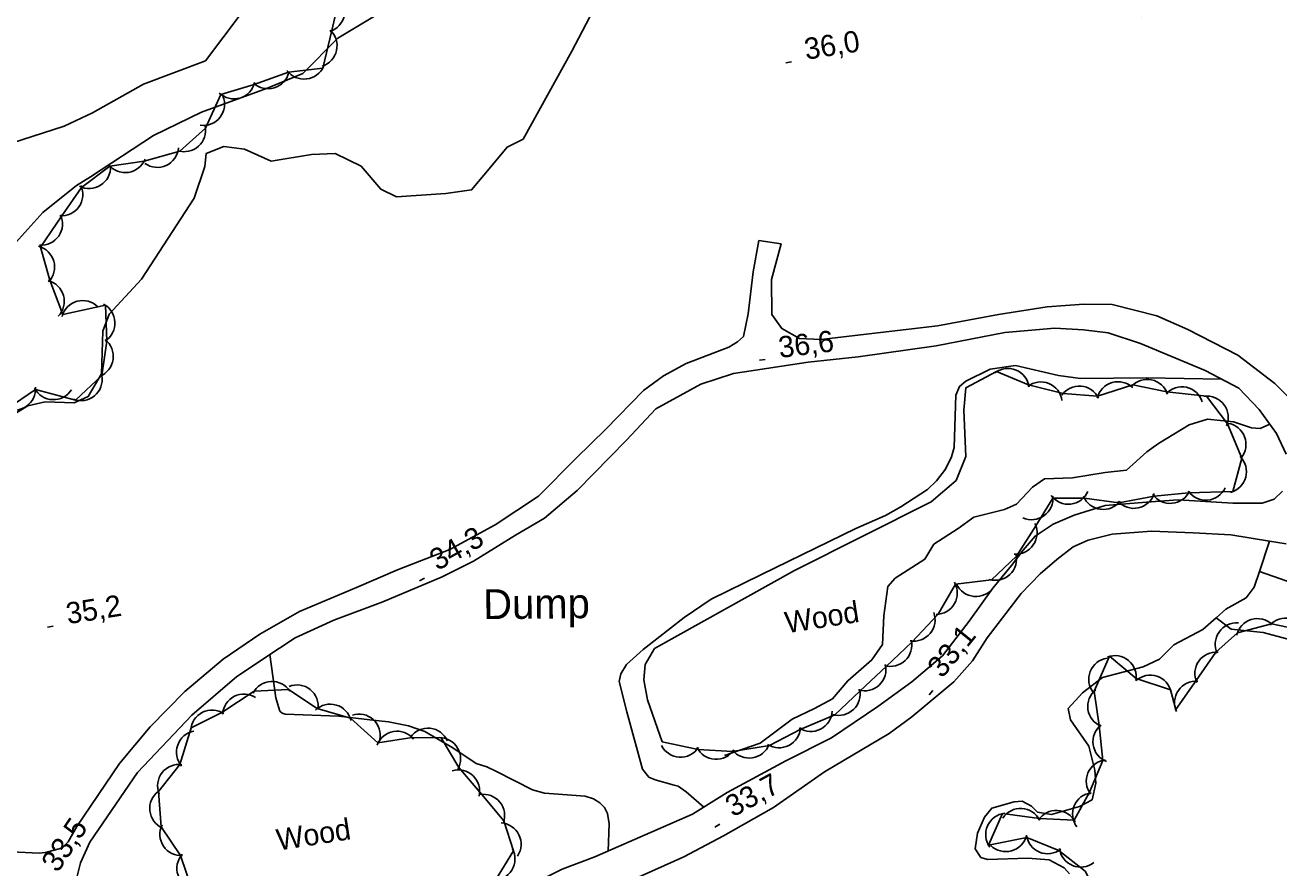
# Model space of a CAD drawing. Extents: x 646142 to 649934, y 5874075 to 5876351.
# Drawn here: x 648068.1 to 648244.3, y 5875844.9 to 5875963.3 of the extents above; entities that cross this region are included whole.
import ezdxf

# ---------------------------------------------------------------- set-up
doc = ezdxf.new("R2010")
doc.units = 0
for name, color, linetype in [('Niveau 2', 7, 'Continuous'), ('Niveau 21', 7, 'Continuous'), ('Niveau 3', 7, 'Continuous'), ('Niveau 44', 7, 'Continuous'), ('Niveau 57', 7, 'Continuous')]:
    doc.layers.add(name, color=color, linetype=linetype)

msp = doc.modelspace()

# ---------------------------------------------------------------- linework, layer by layer
at = {"layer": 'Niveau 2'}
for points in [[(648193.92, 5875992.1), (648191.37, 5875992.54), (648185.64, 5875992.74), (648180.45, 5875991.72), (648174.68, 5875990.2), (648167.73, 5875987.55), (648161.17, 5875987.29), (648154.81, 5875986.7), (648147.8, 5875984), (648141.4, 5875982.37), (648137.22, 5875980.22), (648132.3, 5875975.6), (648125, 5875970.69), (648118.64, 5875965.39), (648112.07, 5875961.45), (648107.17, 5875956.49), (648102.06, 5875954.38), (648092.92, 5875951.05), (648086.18, 5875947.79), (648077.34, 5875941.95), (648075.36, 5875940.77)], [(647999.36, 5875951.21), (648005.33, 5875949.82), (648014.71, 5875947.41), (648024.29, 5875946.86), (648029.28, 5875944.7), (648038.99, 5875939.33), (648045.26, 5875938.54), (648051.81, 5875939.95), (648058, 5875943.18), (648066.23, 5875946.68), (648073.63, 5875949.07), (648077.62, 5875950.98), (648084.78, 5875954.97), (648093.48, 5875958.28), (648098.38, 5875964.74)], [(648075.36, 5875940.77), (648070.61, 5875936.96), (648062.14, 5875927.59), (648054.38, 5875921.14), (648047.82, 5875918.35), (648041.58, 5875917.48), (648034.55, 5875917.98), (648028.66, 5875918.4), (648023.49, 5875918.53)], [(648166.4, 5875860.67), (648171.42, 5875862.38), (648175.91, 5875865.77), (648179.06, 5875867.27), (648181.59, 5875868.61), (648183.74, 5875871.18), (648187.12, 5875874.13), (648188.61, 5875876.26), (648188.83, 5875880.29), (648189.37, 5875884.4), (648190.43, 5875885.57), (648194.57, 5875888.24), (648195.84, 5875890.35), (648199.28, 5875892.56), (648201.44, 5875894.15), (648205.76, 5875895.23), (648207.47, 5875895.99), (648209.69, 5875898.39), (648211.38, 5875899.55), (648215.31, 5875899.68), (648219.94, 5875900.43), (648222.94, 5875900.78), (648225.77, 5875903.34), (648227.4, 5875904.5), (648231.72, 5875907.12), (648234.28, 5875907.94), (648237.97, 5875907.53), (648240.48, 5875906.72), (648241.72, 5875906.61), (648243.04, 5875907.2)]]:
    msp.add_lwpolyline(points, dxfattribs=at)
at = {"layer": 'Niveau 21'}
for points in [[(648247.34, 5875909.43), (648243.76, 5875912.94), (648238.56, 5875916.9), (648231.55, 5875920.5), (648227.18, 5875922.46), (648220.9, 5875924.05), (648216.9, 5875924.09), (648211.79, 5875923.71), (648204.92, 5875922.61), (648196.36, 5875921.05), (648188.33, 5875920.1), (648179.96, 5875919.12), (648179.96, 5875919.12), (648176.98, 5875919.24), (648174.48, 5875920.66), (648173.08, 5875922.61), (648173.05, 5875927.54), (648174.38, 5875932.56), (648171.27, 5875933.01), (648170.46, 5875928.6), (648169.76, 5875922.71), (648169.09, 5875919.56), (648168.23, 5875918.81), (648167.03, 5875918.03), (648161.04, 5875915.75), (648157.86, 5875914.02), (648155.04, 5875911.97), (648149.74, 5875906.53), (648145.6, 5875902.43), (648140.28, 5875897.1), (648134.18, 5875893.08)], [(648245.34, 5875903.01), (648243.98, 5875905.89), (648241.56, 5875909.26), (648238.71, 5875912.26), (648233.96, 5875914.76), (648224.88, 5875918.55), (648220.32, 5875920.04), (648216.86, 5875920.46), (648212.85, 5875920.73), (648205.82, 5875920.09), (648196.15, 5875918.21), (648185.19, 5875916.7), (648178.17, 5875915.94), (648172.31, 5875915.03), (648167.68, 5875914.34), (648163.11, 5875912.85), (648156.75, 5875909.39)], [(648156.75, 5875909.39), (648152.63, 5875904.95), (648145.73, 5875897.89), (648141.11, 5875893.99), (648137.06, 5875891.62), (648131.16, 5875887.96), (648126.75, 5875885.78), (648118.42, 5875882.28), (648111.52, 5875879.69), (648106.09, 5875877.21), (648103.89, 5875875.74), (648097.91, 5875871.77), (648091.56, 5875866.34), (648083.92, 5875858.29), (648077.21, 5875848.47)], [(648166.81, 5875855.49), (648175.06, 5875859.91), (648181.45, 5875863.15), (648187.98, 5875867.55), (648192.75, 5875871.01), (648197.05, 5875874.67), (648200.8, 5875879.55), (648202.59, 5875882.03), (648204.12, 5875884.16), (648206.74, 5875887.35), (648208.4, 5875889.54), (648210.08, 5875891.5), (648212.59, 5875893.19), (648215.58, 5875894.45), (648219.94, 5875895.81), (648225.73, 5875896.25), (648230.17, 5875896.59), (648237.86, 5875896.14), (648241.98, 5875896.1), (648243.65, 5875896.69), (648244.82, 5875897.81)], [(648134.18, 5875893.08), (648127.8, 5875889.61), (648120.46, 5875886.76), (648114.7, 5875884.25), (648106.71, 5875880.89), (648101.1, 5875877.71), (648095.98, 5875874.22), (648090.6, 5875869.67), (648085.7, 5875864.7), (648081.39, 5875859.55), (648075.41, 5875850.71), (648074.2, 5875848.55), (648073.23, 5875847.67), (648070.99, 5875847.04), (648070.13, 5875846.97)], [(648153.49, 5875843.22), (648160.69, 5875846.41), (648166.3, 5875849.37), (648173.32, 5875853.35), (648180.49, 5875858.37), (648189.58, 5875863.77), (648192.73, 5875866.08), (648198.65, 5875871.01), (648201.29, 5875873.96), (648203.33, 5875877.22), (648208.12, 5875883.44), (648210.78, 5875886.17), (648213.14, 5875888.19), (648215.41, 5875889.97), (648217.51, 5875890.93), (648220.88, 5875891.76), (648226.45, 5875892.18), (648232.3, 5875891.94), (648237.58, 5875891.65), (648243.01, 5875890.77), (648245.34, 5875890.4)], [(648070.13, 5875846.97), (648066.24, 5875847.14), (648064.71, 5875849.99), (648062.19, 5875854.09), (648059.65, 5875858.2), (648055.54, 5875864.1), (648052.38, 5875867.91), (648049.88, 5875870.27), (648046.63, 5875873.02), (648041.11, 5875877.11), (648039.18, 5875878.31), (648034.53, 5875881.02), (648029.1, 5875884.01), (648022.94, 5875886.91), (648018.72, 5875888.51), (648013.13, 5875890.16), (648008.67, 5875890.83)], [(648076.55, 5875805.55), (648078.55, 5875804.9), (648080.72, 5875805.07), (648095.59, 5875810.12), (648102.96, 5875812.75), (648109.06, 5875815.4), (648112.43, 5875817.84), (648116.7, 5875822.08), (648119.89, 5875825.31), (648125.57, 5875832.07), (648128.96, 5875835.77), (648131.12, 5875837.43), (648134.07, 5875839.38), (648138.44, 5875842.13), (648143.63, 5875844.71), (648148.2, 5875846.43), (648154.51, 5875849.21), (648161.94, 5875852.42), (648166.81, 5875855.49)], [(648077.21, 5875848.47), (648075.9, 5875845.58), (648075.22, 5875842.76), (648074.65, 5875837.94), (648072.56, 5875823.89), (648072.28, 5875819.68), (648072.21, 5875818.05), (648072.26, 5875810.84), (648072.32, 5875809.91), (648072.43, 5875809.4), (648072.98, 5875808.33), (648074.08, 5875806.95), (648074.91, 5875806.31), (648076.55, 5875805.55)]]:
    msp.add_lwpolyline(points, dxfattribs=at)
at = {"layer": 'Niveau 3'}
for p, q in [((648175.04, 5875958), (648175.83, 5875958.13)), ((648171.33, 5875916.2), (648172.12, 5875916.3)), ((648123.56, 5875885.19), (648124.25, 5875885.58)), ((648071.29, 5875878.71), (648072.08, 5875878.83)), ((648195.17, 5875869.19), (648195.68, 5875869.81)), ((648165.05, 5875850.62), (648165.75, 5875851))]:
    msp.add_line(p, q, dxfattribs=at)
at = {"layer": 'Niveau 44'}
for points in [[(648065.61, 5875909.36), (648069.61, 5875912.1), (648075.21, 5875910.61), (648078.94, 5875914.08), (648079.61, 5875918.89), (648079.41, 5875923.93), (648073.42, 5875922.65), (648071.63, 5875927.44), (648070.31, 5875932.11), (648073.31, 5875936.47), (648076.07, 5875940.46), (648080.06, 5875943.46), (648084.86, 5875944.18), (648089.86, 5875945.57), (648093.49, 5875948.79), (648095.65, 5875953.54), (648100.31, 5875954.92), (648105.14, 5875956.68), (648109.96, 5875957.23), (648111.26, 5875962.52), (648112.32, 5875967.25)], [(648157.68, 5875862.61), (648155.59, 5875868.51), (648155.09, 5875871.32), (648155.28, 5875873.45), (648156.57, 5875875.68), (648176.24, 5875886.65), (648195.48, 5875896.33), (648198.96, 5875899.3), (648200.36, 5875902.69), (648200.07, 5875909.18), (648200.36, 5875912.34), (648204.67, 5875914.6)], [(648157.68, 5875862.61), (648162.72, 5875861.52), (648167.56, 5875861.22), (648172.75, 5875862.07), (648177.07, 5875864.3), (648181.94, 5875866.36), (648185.46, 5875869.7), (648189.2, 5875873.24), (648192.73, 5875876.57), (648196.47, 5875880.51), (648198.88, 5875884.72), (648203.93, 5875885.33), (648207.45, 5875888.68), (648210.18, 5875892.95), (648212.58, 5875896.81), (648217.01, 5875896.8), (648221.83, 5875896.18), (648226.81, 5875897.12), (648231.65, 5875897.55), (648237.84, 5875897.74), (648239.11, 5875902.43), (648237.09, 5875907.29), (648234.15, 5875911.16), (648228.57, 5875911.74), (648223.82, 5875912.74), (648218.86, 5875911.14), (648214.02, 5875911.54), (648209.16, 5875912.76), (648204.67, 5875914.6)], [(648248.04, 5875878.17), (648243.29, 5875879.19), (648238.5, 5875877.88), (648235.47, 5875875.2), (648232.69, 5875871.22), (648229.83, 5875867.12), (648229.12, 5875869.89), (648224.27, 5875871.49), (648220.55, 5875874.61), (648218.36, 5875869.7), (648219.08, 5875864.9), (648219.59, 5875859.98), (648217.7, 5875855.51), (648215.56, 5875851.57), (648210.71, 5875851.84), (648205.49, 5875852.51), (648203.54, 5875848.06), (648208.92, 5875849.15), (648213.42, 5875847.32), (648217.09, 5875844.44), (648219.46, 5875840.03), (648221.76, 5875835.76)], [(648134.22, 5875843.15), (648136.75, 5875847.29), (648135.43, 5875851.47), (648132.33, 5875855.21), (648129.08, 5875858.99), (648126.62, 5875863.17), (648122.51, 5875863.21), (648117.72, 5875862.43), (648113.84, 5875865.9), (648109.17, 5875867.25), (648105.17, 5875869.96), (648100.32, 5875869.71), (648095.79, 5875866.73), (648091.46, 5875864.54), (648089.86, 5875859.41), (648086.87, 5875855.59), (648087.26, 5875850.64), (648089.96, 5875846.6), (648091.63, 5875841.81)]]:
    msp.add_lwpolyline(points, dxfattribs=at)
for centre, start, end in [((648110.07, 5875965.27), 287.334, 47.3119), ((648108.97, 5875960.39), 287.334, 47.3119), ((648107.35, 5875958.7), 216.5244, 336.5023), ((648097.48, 5875955.92), 226.4884, 346.4663), ((648102.28, 5875957.34), 226.4884, 346.4663), ((648093.16, 5875952.18), 262.3211, 22.299), ((648090.5, 5875948.5), 251.6312, 11.6092), ((648086.7, 5875946.3), 234.932, 354.9099), ((648077.14, 5875943.33), 242.5317, 2.5096), ((648082.2, 5875945.56), 218.4931, 338.471), ((648073.24, 5875939.47), 265.284, 25.262), ((648070.39, 5875935.36), 265.284, 25.262), ((648069.28, 5875929.3), 315.8259, 75.8039), ((648070.64, 5875924.48), 315.8259, 75.8039), ((648076.23, 5875921.59), 45.3166, 165.2946), ((648077.76, 5875921.43), 302.6596, 62.6375), ((648077.53, 5875916.73), 292.1044, 52.0824), ((648206.25, 5875912.05), 7.6852, 127.6632), ((648075.97, 5875913.52), 249.4018, 9.3797), ((648210.87, 5875910.15), 7.6852, 127.6632), ((648221.73, 5875910.18), 46.4075, 166.3854), ((648225.83, 5875910.51), 18.0618, 138.0398), ((648066.61, 5875912.19), 244.4075, 4.3854), ((648072.11, 5875913.66), 207.8838, 327.8618), ((648216.29, 5875909.58), 25.2957, 145.2736), ((648230.7, 5875909.47), 17.2892, 137.2672), ((648234.22, 5875908.16), 337.1879, 97.1659), ((648236.71, 5875904.37), 320.9539, 80.9318), ((648236.77, 5875900.54), 284.8633, 44.8412), ((648209.58, 5875896.8), 246.0561, 6.034), ((648214.74, 5875898.97), 216.657, 336.6349), ((648219.64, 5875898.24), 202.6414, 322.6194), ((648223.95, 5875898.39), 221.9315, 341.9094), ((648229.07, 5875899.09), 215.0595, 335.0374), ((648234.05, 5875899.53), 215.0595, 335.0374), ((648207.35, 5875891.95), 265.5189, 25.4969), ((648204.47, 5875888.28), 253.6621, 13.64), ((648196.14, 5875883.49), 270.2727, 30.2506), ((648201.78, 5875886), 204.3184, 324.2963), ((648193.01, 5875879.73), 260.3064, 20.2843), ((648241.33, 5875876.9), 46.9317, 166.9096), ((648245.3, 5875876.95), 17.8771, 137.855), ((648238.39, 5875876.3), 85.1188, 205.0968), ((648189.75, 5875876.19), 253.4267, 13.4047), ((648220.61, 5875871.37), 98.2681, 218.2461), ((648221.28, 5875871.7), 350.1162, 110.0941), ((648235.53, 5875872.2), 85.1188, 205.0968), ((648186.12, 5875872.75), 253.4267, 13.4047), ((648102.84, 5875868.07), 33.0021, 152.9801), ((648226.26, 5875868.96), 11.9176, 131.8955), ((648232.67, 5875868.1), 85.1188, 205.0968), ((648098.89, 5875866.31), 56.7469, 176.7249), ((648106.33, 5875867.59), 351.5778, 111.5557), ((648182.49, 5875869.31), 253.4267, 13.4047), ((648220.47, 5875867.56), 128.4689, 248.4468), ((648111.02, 5875864.88), 13.8772, 133.8551), ((648094.42, 5875864.06), 56.7988, 176.7768), ((648115.06, 5875863.49), 348.1919, 108.1698), ((648178.55, 5875867.04), 237.2749, 357.2529), ((648092.41, 5875861.14), 100.5595, 220.5374), ((648120.4, 5875861.08), 39.2772, 159.2552), ((648124.74, 5875861.51), 23.6588, 143.6368), ((648174.1, 5875864.75), 237.2749, 357.2529), ((648221.2, 5875862.61), 128.4689, 248.4468), ((648126.33, 5875860.19), 330.4423, 90.4202), ((648160.25, 5875863.43), 206.5491, 326.527), ((648169.9, 5875863.3), 218.6807, 338.6586), ((648165.24, 5875863.13), 206.5491, 326.527), ((648089.75, 5875856.41), 81.9794, 201.9573), ((648129.01, 5875855.65), 346.2517, 106.2296), ((648220.27, 5875857.06), 97.1156, 217.0935), ((648088.65, 5875853.22), 126.3069, 246.2848), ((648132.53, 5875852.22), 339.6862, 99.6641), ((648218.33, 5875852.45), 97.1156, 217.0935), ((648208.04, 5875850.23), 26.8119, 146.7898), ((648206.13, 5875849.57), 96.2558, 216.2338), ((648213.04, 5875849.95), 26.8119, 146.7898), ((648090.08, 5875849.6), 153.6963, 273.6742), ((648134.84, 5875848.21), 326.3488, 86.3267), ((648205.96, 5875850.16), 225.3312, 345.3091), ((648211.84, 5875849.87), 187.855, 307.8329), ((648092.47, 5875844.82), 138.8186, 258.7966), ((648133.98, 5875846.14), 268.5248, 28.5028), ((648216.47, 5875847.99), 187.855, 307.8329)]:
    msp.add_arc(centre, 3, start, end, dxfattribs=at)
at = {"layer": 'Niveau 57'}
for points in [[(648138.14, 5875947.25), (648144.99, 5875959.63), (648148.46, 5875966.31), (648150.89, 5875970.16), (648153.65, 5875972.97), (648157.01, 5875975.35), (648158.73, 5875976.37), (648162.43, 5875976.87), (648166.97, 5875976.5), (648189.6, 5875971.47), (648201.85, 5875967.53), (648211.21, 5875968.42), (648215.24, 5875968.14), (648225.04, 5875964.5)], [(648063.91, 5875907.04), (648068.53, 5875909.79), (648070.97, 5875910.35), (648075.01, 5875910.22), (648077.02, 5875911.12), (648078.88, 5875914.3), (648079.08, 5875920.27), (648079.97, 5875922.67), (648084.51, 5875927.58), (648091.88, 5875938.95), (648093.4, 5875943.43), (648093.58, 5875945.27), (648096.07, 5875946.22), (648098.98, 5875945.87), (648102.72, 5875944.18), (648108.37, 5875945.09), (648111.7, 5875945.27), (648115.35, 5875943.47), (648118.11, 5875940.24), (648120.34, 5875939.14), (648127.28, 5875939.63), (648130.87, 5875940.12), (648133.58, 5875943.39), (648135.86, 5875946.14), (648138.14, 5875947.25)], [(648163.52, 5875853.41), (648161.04, 5875855.57), (648159.92, 5875856.36), (648159.37, 5875856.52), (648156.68, 5875857.23), (648155.81, 5875857.64), (648154.92, 5875858.77), (648152.68, 5875866.8), (648151.6, 5875871.05), (648151.84, 5875872.15), (648152.65, 5875873.45), (648154.98, 5875875.56), (648160.74, 5875880.05), (648164.54, 5875882.62), (648171.61, 5875886.08), (648184.87, 5875892.54), (648189.04, 5875894.37), (648191.19, 5875895.61), (648194.95, 5875898.05), (648196.23, 5875899.27), (648197.47, 5875900.88), (648198.33, 5875902.64), (648198.68, 5875903.95), (648198.94, 5875911.28), (648199.45, 5875912.53), (648200.35, 5875913.25), (648203.76, 5875914.95), (648207.33, 5875915.46), (648213.36, 5875914.08), (648216.46, 5875913.62), (648225.74, 5875913.75), (648236.32, 5875913.52)], [(648243.01, 5875890.77), (648241.61, 5875886.54), (648240.87, 5875884.3), (648239.72, 5875882.83), (648236.87, 5875881.24), (648235.51, 5875880.02), (648233.66, 5875878.35), (648229.59, 5875876.21), (648227.57, 5875874.22), (648225.25, 5875873.12), (648219.53, 5875871.65), (648216.72, 5875869.49), (648214.71, 5875867.27), (648215.06, 5875865.69), (648217.62, 5875861.98), (648218.45, 5875858.6), (648218.59, 5875856.77), (648218.08, 5875854.44), (648216.32, 5875853.5), (648212.4, 5875852.4), (648210.43, 5875852.71), (648209.57, 5875853.56), (648208.26, 5875854.26), (648207.12, 5875854.18), (648203.99, 5875853.25), (648202.94, 5875852.02), (648201.96, 5875849.76), (648201.67, 5875847.56), (648202.45, 5875846.36), (648203.38, 5875846.08), (648209.03, 5875846.23), (648212.03, 5875846), (648214.17, 5875844.9), (648214.92, 5875844.04)], [(648241.61, 5875886.54), (648245.37, 5875885.22), (648250.78, 5875883.22), (648254.8, 5875882.84), (648259.19, 5875882.26), (648262.61, 5875880.79), (648264.24, 5875878.85), (648265.04, 5875875.82), (648264.6, 5875874.06), (648263.22, 5875868.1), (648261, 5875867.24), (648258.29, 5875866.81), (648256.86, 5875867.62), (648256.65, 5875868.86), (648257.59, 5875870.08), (648257.4, 5875871.1), (648254.64, 5875871.35), (648252.61, 5875872.46), (648247.39, 5875876.54), (648242.14, 5875877.97), (648237.65, 5875878.43), (648235.51, 5875880.02)], [(648150.06, 5875847.25), (648150.22, 5875851.09), (648149.96, 5875852.51), (648149.54, 5875853.34), (648148.92, 5875854.03), (648147.99, 5875854.59), (648146.83, 5875854.95), (648141.14, 5875855.37), (648139.46, 5875855.85), (648134.4, 5875858.41), (648133.02, 5875859.09), (648131.52, 5875859.53), (648128.26, 5875861.74), (648124.3, 5875864.05), (648122.03, 5875864.83), (648119.21, 5875865.4), (648116.6, 5875865.69), (648112.24, 5875866.19), (648104.7, 5875866.49), (648104.24, 5875866.62), (648103.94, 5875866.92), (648103.36, 5875868.79), (648102.55, 5875874.85)]]:
    msp.add_lwpolyline(points, dxfattribs=at)

# ---------------------------------------------------------------- texts
at = {"layer": 'Niveau 3'}
for s, rotation, p in [('36,0 ', 8.9405, (648177.89, 5875958.41)), ('36,6 ', 7.0313, (648174.19, 5875916.51)), ('34,3 ', 29.417, (648126.08, 5875886.57)), ('35,2 ', 8.9405, (648074.14, 5875879.11)), ('33,1 ', 51.0048, (648197.02, 5875871.4)), ('33,7 ', 28.4108, (648167.6, 5875851.95)), ('33,5 ', 56.201, (648072.71, 5875844.08))]:
    msp.add_text(s, height=3, rotation=rotation, dxfattribs=at).set_placement(p)
at = {"layer": 'Niveau 44'}
for p in [(648175.17, 5875877.83), (648103.72, 5875847.3)]:
    msp.add_text('Wood', height=3, rotation=8.9405, dxfattribs=at).set_placement(p)
at = {"layer": 'Niveau 57'}
msp.add_text('Dump', height=4.2, rotation=0.5571, dxfattribs=at).set_placement((648132.53, 5875879.82))

doc.saveas('drawing.dxf')
